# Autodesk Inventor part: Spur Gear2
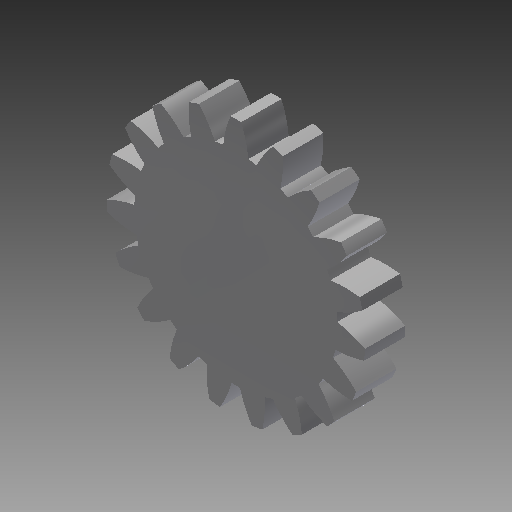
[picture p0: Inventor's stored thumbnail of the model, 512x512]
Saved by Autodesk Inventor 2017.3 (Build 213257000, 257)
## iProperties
Created: 2020-03
Part Number: Spur Gear2
Material: Steel
Document SubType Name: Modeling
Designer: Tim_G
Categories: <?xml version="1.0" encoding="UTF-16"?> <MemberInstance><Categories><FamilyTemplate><FamilyTemplateParameter ValueType="xs:double" Id="1" ObjectReferenceKey="da
Density: 1 g/cm^3
Appearance: Steel
CustomPartVersion: 1
Author: Tim_G
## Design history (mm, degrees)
sketch "Sketch1"
  geometry: C1 r 15.991 at (0, 0)
  constraints: 1 centre point
  dimensions: "d0" = 31.98165 diameter of C1 (= da_da)
extrude "Extrusion1" new body sketch "Sketch1" distance "d1" = 5 (= da_b); taper "d2" = 0 deg
workplane "Work Plane2"
sketch "Sketch2"
  geometry: C1 r 15.991 at (0, 0) reference; C2 r 14.468 at (0, 0)
  constraints: 1 centre point, 1 coincident
  dimensions: "d3" = 28.93578 diameter of C2 (= da_dw)
feature "Pitch Diameter" sketch "Sketch2" dims "d4" = 10, "d5" = 0
workplane "Work Plane8"
workplane "Work Plane9"
feature "Spur Gear" dims "d5" = 0, "da_b" = 5, "da_d" = 28.93578, "da_aw" = 22.84404, "da_da" = 31.98165, "da_df" = 25.12844, "da_dw" = 28.93578, angle "da_beta" = 0 deg, "da_lefttooth" = 0, "da_righttooth" = 0
body "Solid1"
body "Srf1"
other parameters: "d16" = 22.84404 (= da_aw), "d17" = 0, "d34" = 1.65347 (computed from da_z), "d39" = 0, "d41" = 0, "d43" = 22.84404 (= da_aw), "d46" = 22.84404 (= da_aw), "d47" = 0, "d48" = 0
